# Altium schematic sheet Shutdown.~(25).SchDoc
size A4
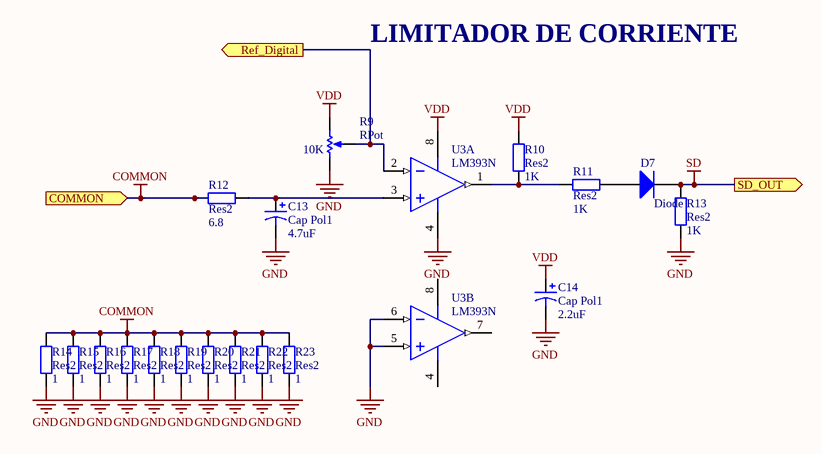
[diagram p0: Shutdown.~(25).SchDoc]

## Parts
C13  Cap Pol1  value 4.7uF  [CAPPR2.5-6.3X5]
C14  Cap Pol1  value 2.2uF  [CAPPR2.5-6.3X5]
D7  Diode  [DO-204AL]
R9  RPot  value 10K  [VR5]
R10  Res2  value 1K  [AXIAL-0.3]
R11  Res2  value 1K  [AXIAL-0.3]
R12  Res2  value 6.8  [AXIAL-0.3]
R13  Res2  value 1K  [AXIAL-0.3]
R14  Res2  value 1  [AXIAL-0.4]
R15  Res2  value 1  [AXIAL-0.4]
R16  Res2  value 1  [AXIAL-0.4]
R17  Res2  value 1  [AXIAL-0.4]
R18  Res2  value 1  [AXIAL-0.4]
R19  Res2  value 1  [AXIAL-0.4]
R20  Res2  value 1  [AXIAL-0.4]
R21  Res2  value 1  [AXIAL-0.4]
R22  Res2  value 1  [AXIAL-0.4]
R23  Res2  value 1  [AXIAL-0.4]
U3  LM393N  [626-05]  (parts A,B of 2)

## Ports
COMMON (in), Ref_Digital (out), SD_OUT (out)

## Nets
COMMON: R12.1 R14.2 R15.2 R16.2 R17.2 R18.2 R19.2 R20.2 R21.2 R22.2 R23.2 ; port COMMON
GND: C13.2 C14.2 R9.1(TOP) R13.1 R14.1 R15.1 R16.1 R17.1 R18.1 R19.1 R20.1 R21.1 R22.1 R23.1 U3.4(GND) U3.5(IN+) U3.6(IN-)
SD: D7.2(K) R13.2 ; port SD_OUT
VDD: C14.1 R9.2(BOT) R10.2 U3.8(V+)
Ref_Digital: R9.3(TAP) U3.2(IN-) ; port Ref_Digital
NetC13_1: C13.1 R12.2 U3.3(IN+)
NetD7_1: D7.1(A) R11.2
NetR10_1: R10.1 R11.1 U3.1(OUT)

Not connected (* = marked no-connect by the designer): U3 7(OUT)

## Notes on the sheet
- LIMITADOR DE CORRIENTE

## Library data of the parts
C13 = Cap Pol1: Polarized 16V
C14 = Cap Pol1: Polarized Capacitor (Radial)
D7 = Diode: Default Diode
R9 = RPot: Potenciomentro multivuelta; Sim Note: Enter the Resistance value and the set point into parameter fields.; Set Position: 0.5
R10-R13 = Res2: metal film 1/2 W
R14-R23 = Res2: metal film 1W
U3 = LM393N: Dual Comparator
